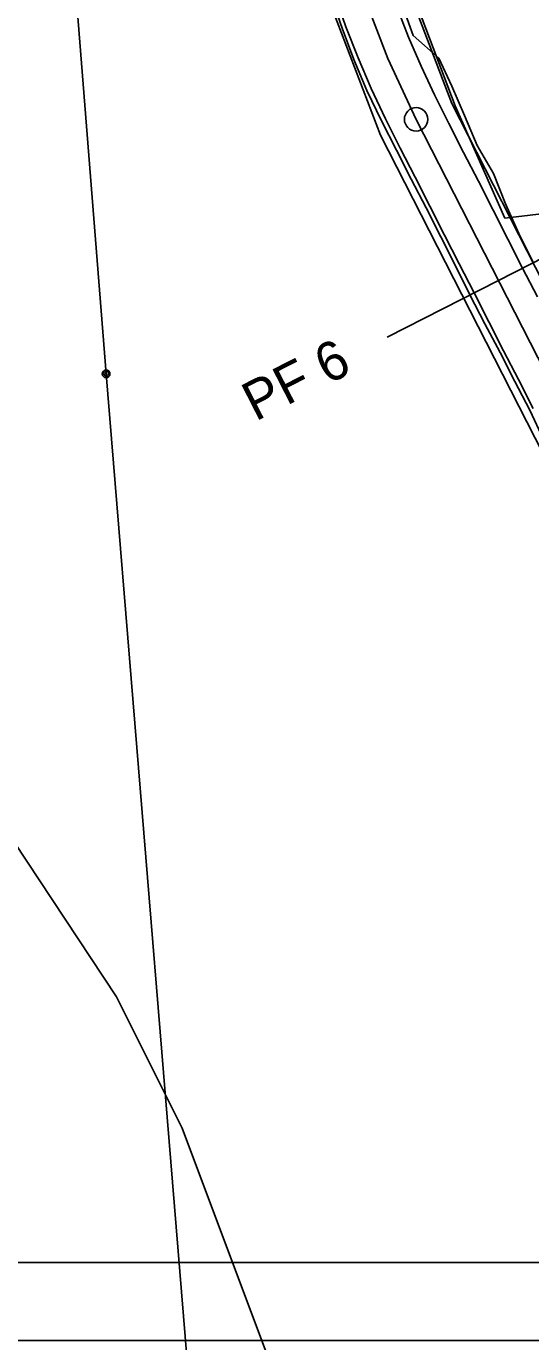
# Model space of a CAD drawing. Extents: x -555887 to -552101, y -1100251 to -1096546.
# Drawn here: x -554271.8 to -554239.5, y -1097395.8 to -1097311.4 of the extents above; entities that cross this region are included whole.
import ezdxf

# ---------------------------------------------------------------- set-up
doc = ezdxf.new("R2010")
doc.units = 0
for name, color, linetype in [('07_ELEKTRO', 7, 'Continuous'), ('PARCELY_cesty', 7, 'Continuous'), ('POLYGONY_SITUACE_PF', 7, 'Continuous'), ('POLYGONY_SITUACE_PF_POPISY', 7, 'Continuous'), ('POLYGONY_SITUACE_PO', 7, 'Continuous'), ('ram_VC6', 7, 'Continuous'), ('vrstevnice', 7, 'Continuous'), ('ZSST', 7, 'Continuous')]:
    doc.layers.add(name, color=color, linetype=linetype)

msp = doc.modelspace()

# ---------------------------------------------------------------- linework, layer by layer
at = {"layer": '07_ELEKTRO'}
msp.add_lwpolyline([(-554275.08, -1097225.88), (-554271.756, -1097269.822), (-554266.687, -1097333.7), (-554260.452, -1097409.538), (-554255.844, -1097467.957), (-554251.063, -1097526.238), (-554246.538, -1097579.501), (-554242.27, -1097628.74), (-554241.833, -1097636.183)], dxfattribs=at)
at = {"layer": 'PARCELY_cesty'}
for points in [[(-554222.14, -1097577.67), (-554219.8, -1097564.758), (-554214.877, -1097501.328), (-554212.926, -1097411.068), (-554213.817, -1097399.017), (-554215.271, -1097391.192), (-554218.761, -1097379.641), (-554223.516, -1097368.495), (-554249.09, -1097318.382), (-554253.811, -1097305.999), (-554255.45, -1097297.231), (-554257.683, -1097277.564), (-554257.68, -1097272.957), (-554254.776, -1097263.93), (-554248.284, -1097256.84), (-554243.382, -1097252.09), (-554241.284, -1097247.986), (-554240.159, -1097243.281), (-554227.326, -1097094.829)], [(-554213.98, -1097572.5), (-554209.03, -1097510.351), (-554207.05, -1097405.63), (-554208.48, -1097387.75), (-554231.63, -1097341.59), (-554244.514, -1097316.349), (-554248.979, -1097304.638), (-554250.502, -1097296.489), (-554252.683, -1097277.283), (-554252.68, -1097273.743), (-554250.86, -1097269.06), (-554235.26, -1097250.21), (-554222.331, -1097095.103)]]:
    msp.add_lwpolyline(points, dxfattribs=at)
at = {"layer": 'POLYGONY_SITUACE_PF'}
for p, q in [((-554241.527, -1097327.703), (-554234.401, -1097324.067)), ((-554248.652, -1097331.34), (-554241.527, -1097327.703))]:
    msp.add_line(p, q, dxfattribs=at)
at = {"layer": 'POLYGONY_SITUACE_PO'}
for p, q in [((-554251.548, -1097311.518), (-554252.256, -1097309.485)), ((-554251.3, -1097311.427), (-554252.005, -1097309.402)), ((-554251.3, -1097311.427), (-554252.005, -1097309.402)), ((-554248.62, -1097313.463), (-554250.154, -1097309.44)), ((-554246.987, -1097311.982), (-554247.67, -1097310.09)), ((-554247.285, -1097312.103), (-554248.015, -1097310.217)), ((-554247.285, -1097312.103), (-554248.015, -1097310.217)), ((-554250.788, -1097313.533), (-554251.548, -1097311.518)), ((-554250.526, -1097313.426), (-554251.3, -1097311.427)), ((-554250.526, -1097313.426), (-554251.3, -1097311.427)), ((-554246.488, -1097313.962), (-554247.285, -1097312.103)), ((-554246.488, -1097313.962), (-554247.285, -1097312.103)), ((-554245.343, -1097313.447), (-554246.987, -1097311.982)), ((-554249.954, -1097315.519), (-554250.788, -1097313.533)), ((-554249.681, -1097315.396), (-554250.526, -1097313.426)), ((-554249.681, -1097315.396), (-554250.526, -1097313.426)), ((-554246.802, -1097317.365), (-554248.62, -1097313.463)), ((-554244.5, -1097315.237), (-554245.343, -1097313.447)), ((-554245.626, -1097315.791), (-554246.488, -1097313.962)), ((-554245.626, -1097315.791), (-554246.488, -1097313.962)), ((-554243.697, -1097317.116), (-554244.5, -1097315.237)), ((-554249.032, -1097317.465), (-554249.954, -1097315.519)), ((-554248.767, -1097317.335), (-554249.681, -1097315.396)), ((-554248.767, -1097317.335), (-554249.681, -1097315.396)), ((-554244.703, -1097317.629), (-554245.626, -1097315.791)), ((-554244.703, -1097317.629), (-554245.626, -1097315.791)), ((-554248.067, -1097319.346), (-554249.032, -1097317.465)), ((-554247.82, -1097319.22), (-554248.767, -1097317.335)), ((-554247.82, -1097319.22), (-554248.767, -1097317.335)), ((-554221.25, -1097367.435), (-554246.802, -1097317.365)), ((-554243.756, -1097319.485), (-554244.703, -1097317.629)), ((-554243.756, -1097319.485), (-554244.703, -1097317.629)), ((-554242.877, -1097319.036), (-554243.697, -1097317.116)), ((-554247.11, -1097321.197), (-554248.067, -1097319.346)), ((-554246.873, -1097321.076), (-554247.82, -1097319.22)), ((-554246.873, -1097321.076), (-554247.82, -1097319.22)), ((-554241.841, -1097320.847), (-554242.877, -1097319.036)), ((-554242.809, -1097321.341), (-554243.756, -1097319.485)), ((-554242.809, -1097321.341), (-554243.756, -1097319.485)), ((-554245.926, -1097322.932), (-554246.873, -1097321.076)), ((-554245.926, -1097322.932), (-554246.873, -1097321.076)), ((-554241.073, -1097322.794), (-554241.841, -1097320.847)), ((-554246.156, -1097323.049), (-554247.11, -1097321.197)), ((-554241.862, -1097323.196), (-554242.809, -1097321.341)), ((-554241.862, -1097323.196), (-554242.809, -1097321.341)), ((-554240.219, -1097324.697), (-554241.073, -1097322.794)), ((-554245.219, -1097324.909), (-554246.156, -1097323.049)), ((-554244.979, -1097324.787), (-554245.926, -1097322.932)), ((-554244.979, -1097324.787), (-554245.926, -1097322.932)), ((-554240.915, -1097325.052), (-554241.862, -1097323.196)), ((-554240.915, -1097325.052), (-554241.862, -1097323.196)), ((-554244.277, -1097326.768), (-554245.219, -1097324.909)), ((-554244.032, -1097326.643), (-554244.979, -1097324.787)), ((-554244.032, -1097326.643), (-554244.979, -1097324.787)), ((-554239.968, -1097326.908), (-554240.915, -1097325.052)), ((-554239.968, -1097326.908), (-554240.915, -1097325.052)), ((-554239.284, -1097326.558), (-554240.219, -1097324.697)), ((-554243.35, -1097328.634), (-554244.277, -1097326.768)), ((-554243.085, -1097328.499), (-554244.032, -1097326.643)), ((-554243.085, -1097328.499), (-554244.032, -1097326.643)), ((-554239.021, -1097328.763), (-554239.968, -1097326.908)), ((-554239.021, -1097328.763), (-554239.968, -1097326.908)), ((-554242.401, -1097330.488), (-554243.35, -1097328.634)), ((-554242.138, -1097330.354), (-554243.085, -1097328.499)), ((-554242.138, -1097330.354), (-554243.085, -1097328.499)), ((-554241.191, -1097332.21), (-554242.138, -1097330.354)), ((-554241.191, -1097332.21), (-554242.138, -1097330.354)), ((-554241.415, -1097332.324), (-554242.401, -1097330.488)), ((-554240.48, -1097334.186), (-554241.415, -1097332.324)), ((-554240.244, -1097334.065), (-554241.191, -1097332.21)), ((-554240.244, -1097334.065), (-554241.191, -1097332.21)), ((-554239.516, -1097336.033), (-554240.48, -1097334.186)), ((-554239.297, -1097335.921), (-554240.244, -1097334.065)), ((-554239.297, -1097335.921), (-554240.244, -1097334.065)), ((-554238.628, -1097337.918), (-554239.516, -1097336.033))]:
    msp.add_line(p, q, dxfattribs=at)
msp.add_circle((-554246.802, -1097317.365), 0.75, dxfattribs=at)
at = {"layer": 'ram_VC6'}
for points in [[(-553956.64, -1096765.72), (-554313.64, -1096765.72), (-554313.64, -1097395.72), (-553956.64, -1097395.72)], [(-553961.64, -1096770.72), (-554308.64, -1096770.72), (-554308.64, -1097390.72), (-553961.64, -1097390.72)]]:
    msp.add_lwpolyline(points, close=True, dxfattribs=at)
for points in [[(-553956.64, -1096765.72), (-554313.64, -1096765.72), (-554313.64, -1097395.72), (-553956.64, -1097395.72), (-553956.64, -1096765.72)], [(-553956.64, -1096765.72), (-554313.64, -1096765.72), (-554313.64, -1097395.72), (-553956.64, -1097395.72), (-553956.64, -1096765.72)], [(-553961.64, -1097390.72), (-554308.64, -1097390.72), (-554308.64, -1096770.72), (-553961.64, -1096770.72), (-553961.64, -1097390.72)], [(-553961.64, -1097185.72), (-553961.64, -1097390.72), (-554308.64, -1097390.72), (-554308.64, -1096770.72), (-553961.64, -1096770.72), (-553961.64, -1096975.72), (-553961.64, -1097185.72)]]:
    msp.add_lwpolyline(points, dxfattribs=at)
at = {"layer": 'vrstevnice'}
msp.add_lwpolyline([(-554443.499, -1097167.35), (-554428.329, -1097192.26), (-554413.309, -1097220.06), (-554400.529, -1097238.88), (-554391.259, -1097249.97), (-554390.419, -1097250.25), (-554390.559, -1097251.09), (-554364.869, -1097276.65), (-554344.929, -1097292.8), (-554344.929, -1097293.36), (-554328.779, -1097306.56), (-554297.469, -1097333.8), (-554286.799, -1097344.33), (-554279.209, -1097353.74), (-554266.009, -1097373.68), (-554261.799, -1097382.1), (-554233.019, -1097458.91), (-554220.099, -1097502.44), (-554215.179, -1097512.13), (-554211.529, -1097517.32), (-554206.619, -1097521.11), (-554200.719, -1097522.94), (-554190.329, -1097523.08), (-554168.989, -1097521.25)], dxfattribs=at)
at = {"layer": 'ZSST'}
for points in [[(-554251.36, -1097267.7), (-554252.11, -1097269.27), (-554251.5, -1097280.08), (-554251.04, -1097288.1), (-554250.25, -1097295.24), (-554249.69, -1097299.01), (-554247.58, -1097307.79), (-554244.29, -1097316.49), (-554241.12, -1097323.71)], [(-554271.756, -1097269.822), (-554266.687, -1097333.7), (-554260.452, -1097409.538), (-554255.844, -1097467.957), (-554251.063, -1097526.238), (-554246.538, -1097579.501)], [(-554204.87, -1097352.16), (-554219.91, -1097332.14), (-554226.22, -1097326.45), (-554228.96, -1097324.6), (-554235.88, -1097323.08), (-554241.12, -1097323.71)]]:
    msp.add_lwpolyline(points, dxfattribs=at)
for radius in [0.25, 0.158, 0.05]:
    msp.add_circle((-554266.687, -1097333.7), radius, dxfattribs=at)

# ---------------------------------------------------------------- texts
at = {"layer": 'POLYGONY_SITUACE_PF_POPISY'}
msp.add_text('PF 6', height=2.5, rotation=27.03664, dxfattribs=at).set_placement((-554257.105, -1097336.776))

doc.saveas('drawing.dxf')
